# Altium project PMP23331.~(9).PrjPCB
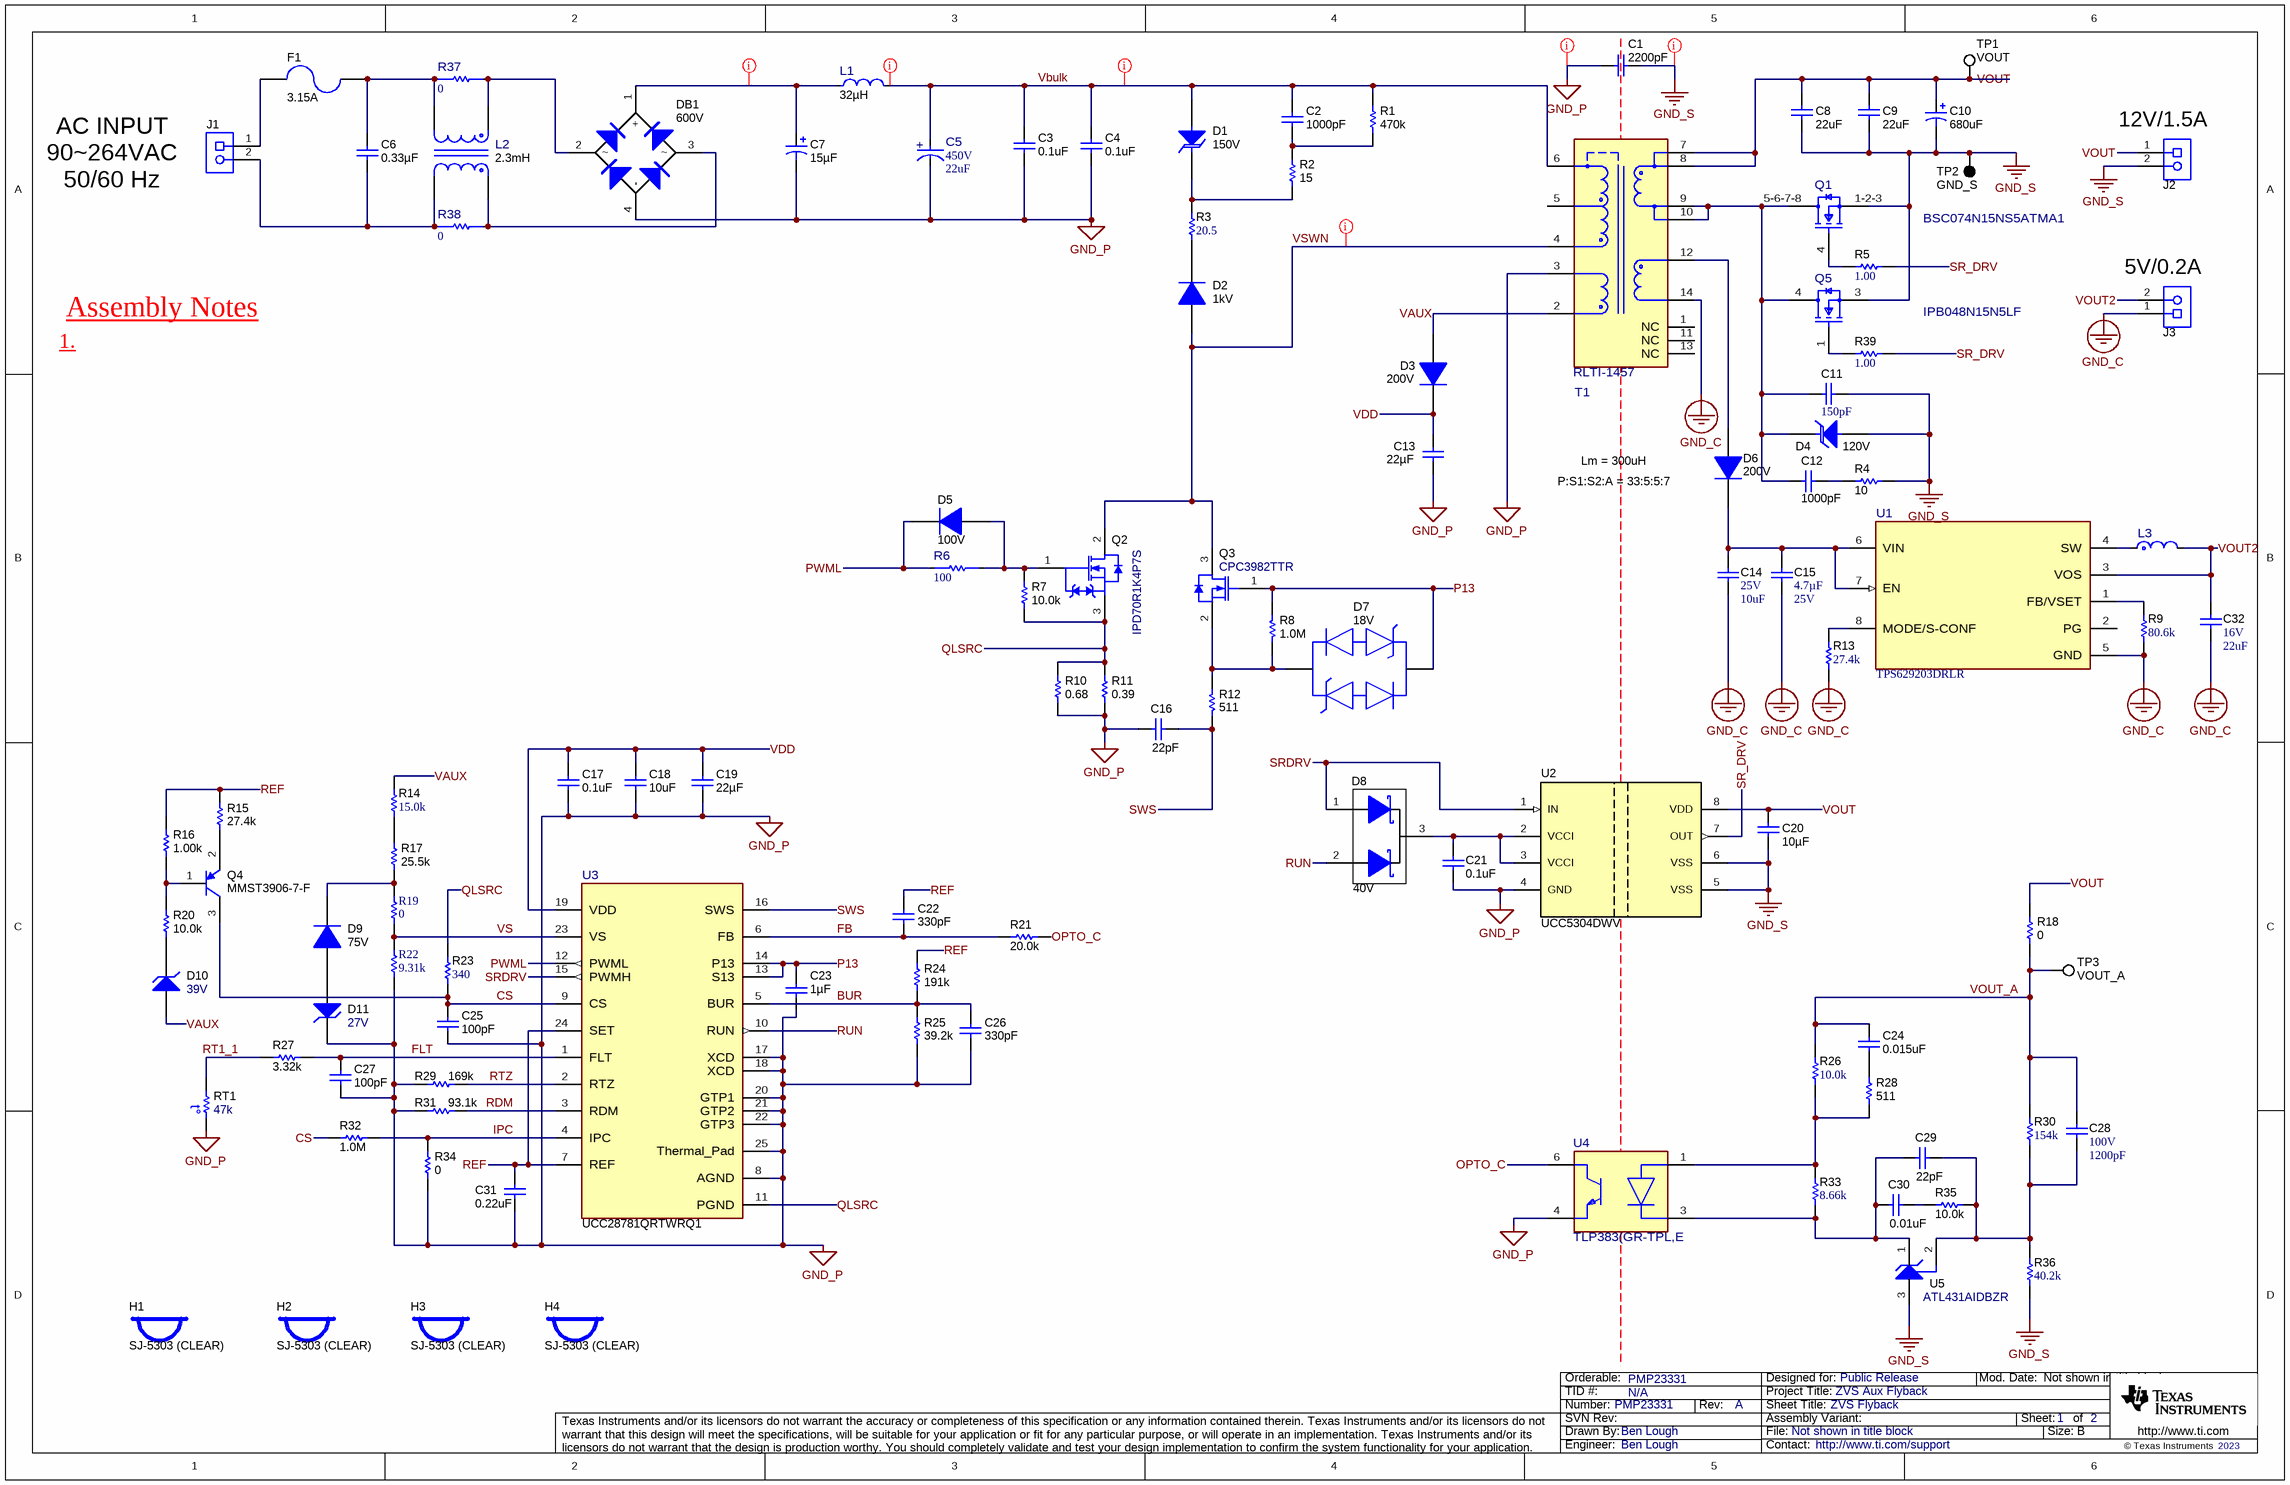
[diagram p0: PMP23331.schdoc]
=Drawn By: Ben Lough; CopyrightYear: 2023; EVM_orderable: PMP23331; PCB_Layout: Ben Lough; PCB_Rev: A; PRJ_Customer: Public Release; PRJ_Engineer: Ben Lough; PRJ_Number: PMP23331; PRJ_Title: ZVS Aux Flyback; SCH_Rev: A; TechSupport: http://www.ti.com/support; TID: N/A
1 sheet, 109 parts. Net scope: global (net labels, ports and power ports of the same name join across sheets).
Board file: PMP23331C.PcbDoc

## Sheet PMP23331.schdoc: ZVS Flyback
size 431 x 279 mm; Date: Not shown in title block; ApprovedBy: Not shown in title block; CheckedBy: Not shown in title block; Author: Not shown in title block; CompanyName: Not shown in title block; DrawnBy: Ben Lough; Engineer: Not shown in title block; Organization: Not shown in title block; Address1: Not shown in title block; Address2: Not shown in title block; Address3: Not shown in title block; Address4: Not shown in title block; DocumentNumber: 1; Revision: Use project parameter SCH_Rev; SheetNumber: 1; SheetTotal: 2; PageSetup: Record=PageOptions¦CenterHorizontal=True¦CenterVertical=True¦PrintScale=1.00¦XCorrection=1.00¦YCorrection=1.00¦PrintKind=0¦BorderSize=5000000¦LeftOffset=0¦BottomOffset=0¦Orientation=2¦PaperLength=1000¦PaperWidth=1000¦Scale=100¦PaperSource=15¦PrintQuality=600¦MediaType=1¦DitherType=10¦PaperKind=Letter¦PrintScaleMode=1

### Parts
C1  ValueDisplayed: 2200pF  [C900_9x13]  (hidden comment: C921U222MVVDBA7317)
C2  ValueDisplayed: 1000pF  [1206L]  (hidden comment: GRM31BR72J102KW01L)
C3  ValueDisplayed: 0.1uF  [1210_280]  (hidden comment: C1210C104KBRAC7800)
C4  ValueDisplayed: 0.1uF  [1210_280]  (hidden comment: C1210C104KBRAC7800)
C5  VDC_V: 450V  ValueDisplayed: 22uF  [FP-450BXW22MEFR18X16_RADIAL-MFG]  (hidden comment: 450BXW22MEFR18X16)
C6  ValueDisplayed: 0.33µF  [WCAP-FTX2_1500x850]  (hidden comment: 890324024003)
C7  ValueDisplayed: 15µF  [UVC_1000x1600]  (hidden comment: UVC2G150MPD)
C8  ValueDisplayed: 22uF  [1210_270L]  (hidden comment: GRM32ER71E226KE15L)
C9  ValueDisplayed: 22uF  [1210_270L]  (hidden comment: GRM32ER71E226KE15L)
C10  ValueDisplayed: 680uF  [PSG_1000x1150]  (hidden comment: APSG200ELL681MJB5S)
C11  Cap_F: 150pF  [0805_HV]  (hidden comment: 600F151FT250XT)
C12  ValueDisplayed: 1000pF  [0805L]  (hidden comment: GRM21AR72E102KW01D)
C13  ValueDisplayed: 22µF  [1210L]  (hidden comment: GMK325BJ226MM-P)
C14  VDC_V: 25V  ValueDisplayed: 10uF  [1210_280]  (hidden comment: C1210C106K3RACTU)
C15  Cap_F: 4.7µF  VDC_V: 25V  [0805L]  (hidden comment: CGA4J1X7R1E475K125AC)
C16  ValueDisplayed: 22pF  [0402S]  (hidden comment: GCM1555C1H220JA16D)
C17  ValueDisplayed: 0.1uF  [0402S]  (hidden comment: GRM155R71H104ME14D)
C18  ValueDisplayed: 10uF  [1206_180L]  (hidden comment: C3216X5R1H106K160AB)
C19  ValueDisplayed: 22µF  [1210L]  (hidden comment: GMK325BJ226MM-P)
C20  ValueDisplayed: 10µF  [1206_180L]  (hidden comment: C1206C106J3RACAUTO)
C21  ValueDisplayed: 0.1uF  [0402S]  (hidden comment: GRM155R71H104ME14D)
C22  ValueDisplayed: 330pF  [0402S]  (hidden comment: GRM155R71H331KA01D)
C23  Cap_F: 1µF  [0603S]  (hidden comment: CGA3E1X7R1V105K080AC)
C24  ValueDisplayed: 0.015uF  [0402S]  (hidden comment: GRM155R71H153KA12D)
C25  ValueDisplayed: 100pF  [0402S]  (hidden comment: GRM1555C1H101JA01D)
C26  ValueDisplayed: 330pF  [0402S]  (hidden comment: GRM155R71H331KA01D)
C27  ValueDisplayed: 100pF  [0402S]  (hidden comment: GRM1555C1H101JA01D)
C28  VDC_V: 100V  ValueDisplayed: 1200pF  [0402S]  (hidden comment: GRM155R72A122KA01D)
C29  ValueDisplayed: 22pF  [0402S]  (hidden comment: GCM1555C1H220JA16D)
C30  ValueDisplayed: 0.01uF  [0402S]  (hidden comment: GRM155R71H103KA88D)
C31  ValueDisplayed: 0.22uF  [0402S]  (hidden comment: GRM155R71C224KA12D)
C32  VDC_V: 16V  ValueDisplayed: 22uF  [1210_280]  (hidden comment: GCM32ER71C226KE19L)
D1  VRWM: 150V  [SMA]  (hidden comment: SMAJ150A)
D2  Vr_V: 1kV  [SMA]  (hidden comment: MRA4007T3G)
D3  Vr_V: 200V  [SOD-123H]  (hidden comment: CSFMT104-HF)
D4  value 120V  [SMA]  (hidden comment: SMAJ120A)
D5  Vr_V: 100V  [SOD-323]  (hidden comment: BAS316,115)
D6  Vr_V: 200V  [SOD-123H]  (hidden comment: CSFMT104-HF)
D7  value 18V  [FP-CDSOD323-T18C_SOD323-MFG]  (hidden comment: CDSOD323-T18C)
D8  Vr_V: 40V  [SOT-323]  (hidden comment: BAS40W-05-7-F)
D9  Vr_V: 75V  [SOD-523]  (hidden comment: 1N4148X-TP)
D10  value 39V  [SOD-523]  (hidden comment: BZT585B39T-7)
D11  value 27V  [SOD-323]  (hidden comment: SZMM3Z27VST1G)
DB1  value 600V  [Z4-D]  (hidden comment: Z4DGP406L-HF)
F1  Irating_A: 3.15A  [FUSE_392]  (hidden comment: 39213150000)
H1  SJ-5303 (CLEAR)  [Bumpon_SJ5003Transparent]
H2  SJ-5303 (CLEAR)  [Bumpon_SJ5003Transparent]
H3  SJ-5303 (CLEAR)  [Bumpon_SJ5003Transparent]
H4  SJ-5303 (CLEAR)  [Bumpon_SJ5003Transparent]
J1  ED120/2DS  [On-Shore_ED120_2DS]  (value not drawn)
J2  ED120/2DS  [On-Shore_ED120_2DS]  (value not drawn)
J3  ED120/2DS  [On-Shore_ED120_2DS]  (value not drawn)
L1  Ind_H: 32µH  [FP-7447052_PTH_D10MM0-MFG]  (hidden comment: 7447052)
L2  Ind_H: 2.3mH  [FP-RLTI-1387_PTH_CMC_0IN38_0IN60-MFG]  (hidden comment: RLTI-1387)
L3  XGL3530-332MEC  [FP-XGL3530_SMT_IND_3MM2_3MM5-MFG]  (value not drawn)
Q1  BSC074N15NS5ATMA1  [FP-BSC074N15NS5ATMA1_PG-TSON-8-3-MFG]
Q2  IPD70R1K4P7S  [DPAK]
Q3  CPC3982TTR  [SOT-23L]
Q4  MMST3906-7-F  [SOT-323]
Q5  IPB048N15N5LF  [FP-IPB042N10N3GATMA1_D2PAK-MFG]
R1  ValueDisplayed: 470k  [0805_HV1]  (hidden comment: CRCW0805470KJNEA)
R2  ValueDisplayed: 15  [0805_HV1]  (hidden comment: CRCW080515R0JNEA)
R3  ValueDisplayed: 20.5  [0805_HV]  (hidden comment: CRCW080520R5FKEA)
R4  ValueDisplayed: 10  [1206L]  (hidden comment: CRCW120610R0JNEA)
R5  ValueDisplayed: 1.00  [0402S]  (hidden comment: CSR0402FK1R00)
R6  Res_ohm: 100  [FP-RK73H1JTTD1000F_0603-MFG]  (hidden comment: RK73H1JTTD1000F)
R7  ValueDisplayed: 10.0k  [0402S]  (hidden comment: CRCW040210K0FKED)
R8  ValueDisplayed: 1.0M  [0402S]  (hidden comment: CRCW04021M00JNED)
R9  ValueDisplayed: 80.6k  [0402L]  (hidden comment: CRCW040280K6FKED)
R10  ValueDisplayed: 0.68  [0805_HV1]  (hidden comment: ERJ-6RQFR68V)
R11  ValueDisplayed: 0.39  [1210L]  (hidden comment: MCR25JZHFLR390)
R12  ValueDisplayed: 511  [0402S]  (hidden comment: CRCW0402511RFKED)
R13  ValueDisplayed: 27.4k  [0402L]  (hidden comment: CRCW040227K4FKED)
R14  ValueDisplayed: 15.0k  [0402]  (hidden comment: CRCW040215K0FKED)
R15  ValueDisplayed: 27.4k  [0402S]  (hidden comment: CRCW040227K4FKED)
R16  ValueDisplayed: 1.00k  [0402S]  (hidden comment: CRCW04021K00FKED)
R17  ValueDisplayed: 25.5k  [0402S]  (hidden comment: RC0402FR-0725K5L)
R18  ValueDisplayed: 0  [0402S]  (hidden comment: RC0402JR-070RL)
R19  value 0  [RESC1005X40X25NL05T10]  (hidden comment: RC0402JR-070RL)
R20  ValueDisplayed: 10.0k  [0402S]  (hidden comment: CRCW040210K0FKED)
R21  ValueDisplayed: 20.0k  [0402S]  (hidden comment: CRCW040220K0FKED)
R22  value 9.31k  [RESC1005X40X25LL05T05]  (hidden comment: ERJ-2RKF9311X)
R23  ValueDisplayed: 340  [0402S]  (hidden comment: CRCW0402340RFKED)
R24  ValueDisplayed: 191k  [0402S]  (hidden comment: CRCW0402191KFKED)
R25  ValueDisplayed: 39.2k  [0402S]  (hidden comment: CRCW040239K2FKED)
R26  ValueDisplayed: 10.0k  [0402S]  (hidden comment: RC0402FR-0710KL)
R27  ValueDisplayed: 3.32k  [0402S]  (hidden comment: CRCW04023K32FKED)
R28  ValueDisplayed: 511  [0402S]  (hidden comment: CRCW0402511RFKED)
R29  ValueDisplayed: 169k  [0402S]  (hidden comment: CRCW0402169KFKED)
R30  ValueDisplayed: 154k  [0402L]  (hidden comment: CRCW0402154KFKED)
R31  ValueDisplayed: 93.1k  [0402S]  (hidden comment: CRCW040293K1FKED)
R32  ValueDisplayed: 1.0M  [0402S]  (hidden comment: CRCW04021M00JNED)
R33  ValueDisplayed: 8.66k  [0402S]  (hidden comment: CRCW04028K66FKED)
R34  ValueDisplayed: 0  [0402S]  (hidden comment: CRCW04020000Z0EDHP)
R35  ValueDisplayed: 10.0k  [0402S]  (hidden comment: CRCW040210K0FKED)
R36  ValueDisplayed: 40.2k  [0402L]  (hidden comment: CRCW040240K2FKED)
R37  Res_ohm: 0  [FP-RMCF1206ZT0R00_1206-MFG]  (hidden comment: RMCF1206ZT0R00)
R38  Res_ohm: 0  [FP-RMCF1206ZT0R00_1206-MFG]  (hidden comment: RMCF1206ZT0R00)
R39  ValueDisplayed: 1.00  [0402S]  (hidden comment: CSR0402FK1R00)
RT1  value 47k  [0603S]  (hidden comment: NCP18WB473J03RB)
T1  RLTI-1457  [FP-RLTI-1457_PTH14_0IN93_0IN93-MFG]
TP1  VOUT  [Keystone5012]
TP2  GND_S  [Keystone5011]
TP3  VOUT_A  [Keystone5012]
U1  TPS629203DRLR  [DRL0008A-MFG]
U2  UCC5304DWV  [DWV0008A]
U3  UCC28781QRTWRQ1  [RTW0024B-MFG]
U4  TLP383(GR-TPL,E  [FP-TLP383(GR-TPL,E_SO6-4-MFG]
U5  ATL431AIDBZR  [DBZ0003A_L]

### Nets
GND_C: C14.2 C15.2 C32.2 J3.1 R9.1 R13.1 T1.14(SGND) U1.5(GND)
GND_P: C1.2 C3.1 C4.1 C5.1(CATHODE) C7.2(-) C13.1 C16.1 C17.2 C18.2 C19.1 C21.2 C23.2 C25.2 C26.2 C27.1 C31.2 D11.1(K) DB1.4(-) R10.2 R11.1 R22.1 R25.2 R29.1 R31.1 R34.1 RT1.2 T1.3(PGND) U2.4(GND) U3.8(AGND) U3.17(XCD) U3.18(XCD) U3.20(GTP1) U3.21(GTP2) U3.22(GTP3) U3.25(Thermal_Pad) U4.4(Emitter)
GND_S: C1.1 C8.2 C9.2 C10.2(-) C11.1 C20.2 D4.2(A) J2.2 Q1.1-2-3(S) Q5.3(SOURCE) R4.1 R36.1 TP2.1 U2.5(VSS) U2.6(VSS) U5.3(ANODE)
BUR: C26.1 R24.2 R25.1 U3.5(BUR)
CS: C25.1 Q4.3(C) R23.1 R32.2 U3.9(CS)
FB: C22.2 R21.1 U3.6(FB)
FLT: C27.2 R27.2 U3.1(FLT)
IPC: R32.1 R34.2 U3.4(IPC)
OPTO_C: R21.2 U4.6(Collector)
P13: C23.1 D7.2 Q3.1(G) R8.2 U3.13(S13) U3.14(P13)
PWML: D5.1(K) R6.1 U3.12(PWML)
QLSRC: Q2.3(S) R7.1 R10.1 R11.2 R23.2 U3.11(PGND)
RDM: R31.2 U3.3(RDM)
REF: C22.1 C31.1 R15.1 R16.1 R24.1 U3.7(REF) U3.24(SET)
RT1_1: R27.1 RT1.1
RTZ: R29.2 U3.2(RTZ)
RUN: D8.2(A) U3.10(RUN)
SR_DRV: R5.1 R39.1 U2.7(OUT)
SRDRV: D8.1(A) U2.1(IN) U3.15(PWMH)
SWS: C16.2 R12.1 U3.16(SWS)
VAUX: D3.2(A) D10.2(A) R14.2 T1.2(VAUX)
Vbulk: C2.1 C3.2 C4.2 C5.2(ANODE) D1.2(A) L1.2 R1.2 T1.6(VDC+)
VDD: C13.2 C17.1 C18.1 C19.2 D3.1(K) U3.19(VDD)
VOUT: C8.1 C9.1 C10.1(+) C20.1 J2.1 R18.1 T1.7(12V) T1.8(12V) TP1.1 U2.8(VDD)
VOUT2: C32.1 J3.2 L3.2 U1.3(VOS)
VOUT_A: C24.2 C28.1 R18.2 R26.2 R30.2 TP3.1
VS: R19.1 R22.2 U3.23(VS)
VSWN: D2.2(A) Q2.2(D) Q3.3(D) T1.4(DRAIN)
NetC2_2: C2.2 R1.1 R2.2
NetC6_1: C6.1 J1.2 L2.2 R38.1
NetC6_2: C6.2 F1.1 L2.3 R37.1
NetC7_1: C7.1(+) DB1.1(+) L1.1
NetC11_2: C11.2 C12.2 D4.1(K) Q1.5-6-7-8(D) Q5.4(DRAIN) T1.9(SR_FET) T1.10(SR_FET)
NetC12_1: C12.1 R4.2
NetC14_1: C14.1 C15.1 D6.1(K) U1.6(VIN) U1.7(EN)
NetC21_1: C21.1 D8.3(K) U2.2(VCCI) U2.3(VCCI)
NetC24_1: C24.1 R28.2
NetC28_2: C28.2 C29.2 R30.1 R35.2 R36.2 U5.2(REF)
NetC29_1: C29.1 C30.2 R33.1 U4.3(Cathode) U5.1(CATHODE)
NetC30_1: C30.1 R35.1
NetD1_1: D1.1(K) R2.1 R3.2
NetD2_1: D2.1(K) R3.1
NetD5_2: D5.2(A) Q2.1(G) R6.2 R7.2
NetD6_2: D6.2(A) T1.12(12V)
NetD7_1: D7.1 Q3.2(S) R8.1 R12.2
NetD9_1: D9.1(K) R17.2 R19.2
NetD9_2: D9.2(A) D11.2(A)
NetD10_1: D10.1(K) R20.2
NetDB1_2: DB1.2 L2.4 R37.2
NetDB1_3: DB1.3 L2.1 R38.2
NetF1_2: F1.2 J1.1
NetL3_1: L3.1 U1.4(SW)
NetQ1_4: Q1.4(G) R5.2
NetQ4_1: Q4.1(B) R16.2 R20.1
NetQ4_2: Q4.2(E) R15.2
NetQ5_1: Q5.1(GATE) R39.2
NetR9_2: R9.2 U1.1(FB/VSET)
NetR13_2: R13.2 U1.8(MODE/S-CONF)
NetR14_1: R14.1 R17.1
NetR26_1: R26.1 R28.1 R33.2 U4.1(Anode)

Not connected (* = marked no-connect by the designer): T1 1(NC) 5 11(NC) 13(NC); U1 2(PG)

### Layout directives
net class HV: NetC7_1, Vbulk, VSWN
net class Primary: GND_P
net class Secondary: GND_S

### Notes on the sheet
- 90|64VAC
- AC INPUT
- (near J2) 12V/1.5A
- 50/60 Hz
- Assembly Notes
- (near J3) 5V/0.2A
- 1.
- P:S1:S2:A = 33:5:5:7
- Lm = 300uH

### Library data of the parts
C1 = CMP-0078358-1: CAP, CERM, 2200 pF, X1 400 VAC/Y1 400 VAC, +/- 20%, Y5V, D9xL13mm; Manufacturer: Kemet; Cap_F: 2.2nF; SizeAreaWB_mm2: 121; VAC_X: 400V; SizeArea_mm2: 81; AEC Qualified: N; AEC Category: Q200; Value: 2200pF; TaMax_C: 125°C; SizeZ_mm: 13; TaMin_C: -40°C; SizeY_mm: 9; U/M: EA; AC_Safety: X1Y1; Cap_Case: 9x13mm
C2 = CMP-0008909-2: CAP, CERM, 1000 pF, 630 V, +/- 10%, X7R, 1206; Manufacturer: MuRata; TaMin_C: -55°C; Polarized: N; SizeAreaWB_mm2: 10.92; Value1: Unknown; U/M: EA; Value: 1000pF; TaMax_C: 125°C; SizeZ_mm: 1.35; SizeX_mm: 3.2; SizeY_mm: 1.6; Cap_Case: 1206; Value2: 630V; SizeArea_mm2: 5.12; Cap_F: 1nF; AEC Category: Q200
C3 C4 = CMP-0009076-1: CAP, CERM, 0.1 uF, 630 V, +/- 10%, X7R, 1210; Manufacturer: Kemet; Polarized: N; Value: 0.1uF; U/M: EA; Cap_F: 100nF; Value1: Unknown; VDC_V: 630V; TaMin_C: -55°C; TaMax_C: 125°C; Cap_Case: 1210; SizeArea_mm2: 8; SizeAreaWB_mm2: 14.7; SizeX_mm: 3.2; SizeY_mm: 2.5; SizeZ_mm: 2.8; AEC Category: Q200
C5 = CMP-0088960-1: Cap Aluminum Lytic 22uF 450V 20% (18 X 16mm) Radial 7.5mm 340mA 10000h 105C; Manufacturer: Rubycon; Cap_F: 22µF; Dissipation Factor: 25%; IRMS_A: 850mA; SizeZ_mm: 18mm; Leakage Current: 298uA; Life: 10000Hours; AEC Qualified: No
C6 = CMP-0084596-1: CAP, Film, 0.33 µF, X2 275 VAC, +/- 10%, TH; Manufacturer: Wurth Elektronik; Cap_Case: 15x8.5mm; SizeAreaWB_mm2: 178.5; AEC Qualified: N; SizeX_mm: 15; Cap_F: 330nF; SizeY_mm: 8.5; VAC_X: 275; TaMin_C: -40°C; SizeZ_mm: 14.5; SizeArea_mm2: 127.5; Value: 0.33uF; TaMax_C: 105°C; AEC Category: Q200
C7 = CMP-0860955-2: CAP, AL, 15 µF, 400 V, +/- 20%, AEC-Q200 Grade 2, TH; Manufacturer: Nichicon; SizeArea_mm2: 100; CompType: Capacitor; Value2: 400V; SizeZ_mm: 18; IRMS_A: 180mA; Polarized: Y; SizeX_mm: 10; Value: 15uF; TaMin_C: -40°C; AEC Grade: 2; U/M: EA; SizeAreaWB_mm2: 144; Cap_Case: 10x16; TaMax_C: 105°C; AEC Category: Q200
C8 C9 = CMP-0009224-2: CAP, CERM, 22 uF, 25 V, +/- 10%, X7R, 1210; Manufacturer: MuRata; TaMin_C: -55°C; Polarized: N; SizeAreaWB_mm2: 14.7; Value1: Unknown; U/M: EA; Value: 22uF; TaMax_C: 125°C; SizeZ_mm: 2.7; SizeX_mm: 3.2; SizeY_mm: 2.5; Cap_Case: 1210; Value2: 25V; SizeArea_mm2: 8; Cap_F: 22µF; AEC Category: Q200
C10 = CMP-0012176-3: CAP, Aluminum Polymer, 680 uF, 20 V, +/- 20%, 0.012 ohm, TH; Manufacturer: Chemi-Con; TaMin_C: -55°C; ESR_ohm: 0.012; Polarized: Y; SizeAreaWB_mm2: 144; Value: 680uF; TaMax_C: 105°C; SizeZ_mm: 13; SizeX_mm: 10; Cap_Case: 10x11.5; Value2: 20V; SizeArea_mm2: 100; CompType: Capacitor; AEC Qualified: N; Cap_F: 680µF; IRMS_A: 5.4A; AEC Category: Q200
C11 = CMP-0064943-2: CAP, CERM, 150 pF, 250 V,+/- 10%, X7R, 0805; Manufacturer: TDK; TaMin_C: -55°C; Polarized: N; SizeAreaWB_mm2: 6.75; Value1: Unknown; U/M: EA; Value: 1000pF; TaMax_C: 125°C; SizeZ_mm: 1.45; SizeX_mm: 2; SizeY_mm: 1.25; Cap_Case: 0805; Value2: 250V; SizeArea_mm2: 2.5; AEC Category: Q200
C12 = CMP-0008251-2: CAP, CERM, 1000 pF, 250 V, +/- 10%, X7R, 0805; Manufacturer: MuRata; TaMin_C: -55°C; Polarized: N; SizeAreaWB_mm2: 6.75; Value1: Unknown; U/M: EA; Value: 1000pF; TaMax_C: 125°C; SizeZ_mm: 1.45; SizeX_mm: 2; SizeY_mm: 1.25; Cap_Case: 0805; Value2: 250V; SizeArea_mm2: 2.5; Cap_F: 1nF; AEC Category: Q200
C13 C19 = CMP-0085817-1: CAP, CERM, 22 µF, 35 V,+/- 20%, X5R, 1210; Manufacturer: Taiyo Yuden; Value: 22uF; VDC_V: 35V; SizeZ_mm: 1.35; Cap_Case: 1210; TaMax_C: 85°C; U/M: EA; SizeAreaWB_mm2: 14.7; SizeX_mm: 3.2; SizeArea_mm2: 8; TaMin_C: -55°C; AEC Qualified: N; SizeY_mm: 2.5; AEC Category: Q200
C14 = CMP-0009078-1: CAP, CERM, 10 uF, 25 V, +/- 10%, X7R, 1210; Manufacturer: Kemet; TaMin_C: -55°C; Polarized: N; SizeAreaWB_mm2: 14.7; Value1: Unknown; U/M: EA; Value: 10uF; TaMax_C: 125°C; SizeZ_mm: 2.8; SizeX_mm: 3.2; SizeY_mm: 2.5; Cap_Case: 1210; SizeArea_mm2: 8; Cap_F: 10µF; AEC Category: Q200
C15 = CMP-0076706-1: CAP, CERM, 4.7 µF, 25 V,+/- 10%, X7R, AEC-Q200 Grade 1, 0805; Manufacturer: TDK; SizeAreaWB_mm2: 6.75; SizeArea_mm2: 2.5; AEC Qualified: Y; AEC Category: Q200; Value: 4.7uF; TaMax_C: 125°C; SizeZ_mm: 1.45; AEC Grade: 1; Polarized: N; TaMin_C: -55°C; SizeY_mm: 1.25; U/M: EA; SizeX_mm: 2.0; Cap_Case: 2x1.25x1.25mm
C16 C29 = CMP-0006348-2: CAP, CERM, 22 pF, 50 V, +/- 5%, C0G/NP0, AEC-Q200 Grade 1, 0402; Manufacturer: MuRata; TaMin_C: -55°C; Polarized: N; SizeAreaWB_mm2: 3; Value1: Unknown; U/M: EA; Value: 22pF; TaMax_C: 125°C; SizeZ_mm: 0.6; SizeX_mm: 1; SizeY_mm: 0.5; Cap_Case: 0402; Value2: 50V; AEC Qualified: Y; AEC Category: Q200
C17 C21 = CMP-0006675-2: CAP, CERM, 0.1 uF, 50 V, +/- 20%, X7R, 0402; Manufacturer: MuRata; TaMin_C: -55°C; Polarized: N; SizeAreaWB_mm2: 3; Value1: Unknown; U/M: EA; Value: 0.1uF; TaMax_C: 125°C; SizeZ_mm: 0.6; SizeX_mm: 1; SizeY_mm: 0.5; Cap_Case: 0402; Value2: 50V; Cap_F: 100nF; AEC Category: Q200
C18 = CMP-0008658-2: CAP, CERM, 10 uF, 50 V, +/- 10%, X5R, 1206; Manufacturer: TDK; TaMin_C: -55°C; ESR_ohm: 2.229m; Polarized: N; SizeAreaWB_mm2: 10.92; Value1: 0.002229 ohm; U/M: EA; Value: 10uF; TaMax_C: 85°C; SizeZ_mm: 1.8; SizeX_mm: 3.2; SizeY_mm: 1.6; Cap_Case: 1206_180; Value2: 50V; SizeArea_mm2: 5.12; Cap_F: 10µF; IRMS_A: 4.85932A; AEC Category: Q200
C20 = CMP-0081062-1: CAP, CERM, 10 µF, 25 V,+/- 5%, X7R, AEC-Q200 Grade 1, 1206; Manufacturer: Kemet; TaMin_C: -55°C; Polarized: N; SizeAreaWB_mm2: 10.92; U/M: EA; Value: 10uF; TaMax_C: 125°C; SizeZ_mm: 1.8; SizeX_mm: 3.2; SizeY_mm: 1.6; Cap_Case: 1206_180; Value2: 25V; SizeArea_mm2: 5.12; AEC Qualified: Y; AEC Grade: 1; AEC Category: Q200
C22 C26 = CMP-0006687-2: CAP, CERM, 330 pF, 50 V, +/- 10%, X7R, 0402; Manufacturer: MuRata; TaMin_C: -55°C; Polarized: N; SizeAreaWB_mm2: 3; Value1: Unknown; U/M: EA; Value: 330pF; TaMax_C: 125°C; SizeZ_mm: 0.6; SizeX_mm: 1; SizeY_mm: 0.5; Cap_Case: 0402; Value2: 50V; AEC Category: Q200
C23 = CMP-0007067-4: CAP, CERM, 1 uF, 35 V, +/- 10%, X7R, AEC-Q200 Grade 1, 0603; Manufacturer: TDK; TaMin_C: -55°C; ESR_ohm: 5.522m; Polarized: N; SizeAreaWB_mm2: 4.68; Value1: 0.005522 ohm; U/M: EA; Value: 1uF; TaMax_C: 125°C; SizeZ_mm: 1; SizeX_mm: 1.6; SizeY_mm: 0.8; Cap_Case: 0603; Value2: 35V; SizeArea_mm2: 1.28; AEC Qualified: Y; IRMS_A: 2.21617A; AEC Category: Q200
C24 = CMP-0006679-2: CAP, CERM, 0.015 uF, 50 V, +/- 10%, X7R, 0402; Manufacturer: MuRata; TaMin_C: -55°C; Polarized: N; SizeAreaWB_mm2: 3; Value1: Unknown; U/M: EA; TaMax_C: 125°C; SizeZ_mm: 0.6; SizeX_mm: 1; SizeY_mm: 0.5; Cap_Case: 0402; Value2: 50V; Cap_F: 15nF; AEC Category: Q200
C25 C27 = CMP-0006410-2: CAP, CERM, 100 pF, 50 V, +/- 5%, C0G/NP0, 0402; Manufacturer: MuRata; TaMin_C: -55°C; Polarized: N; SizeAreaWB_mm2: 3; Value1: Unknown; U/M: EA; Value: 100pF; TaMax_C: 125°C; SizeZ_mm: 0.6; SizeX_mm: 1; SizeY_mm: 0.5; Cap_Case: 0402; Value2: 50V; AEC Category: Q200
C28 = CMP-0006700-2: CAP, CERM, 1200 pF, 100 V, +/- 10%, X7R, 0402; Manufacturer: MuRata; TaMin_C: -55°C; Polarized: N; SizeAreaWB_mm2: 3; Value1: Unknown; U/M: EA; Value: 1200pF; TaMax_C: 125°C; SizeZ_mm: 0.6; SizeX_mm: 1; SizeY_mm: 0.5; Cap_Case: 0402; Cap_F: 1.2nF; AEC Category: Q200
C30 = CMP-0006674-2: CAP, CERM, 0.01 uF, 50 V, +/- 10%, X7R, 0402; Manufacturer: MuRata; TaMin_C: -55°C; Polarized: N; SizeAreaWB_mm2: 3; Value1: Unknown; U/M: EA; Value: 0.01uF; TaMax_C: 125°C; SizeZ_mm: 0.6; SizeX_mm: 1; SizeY_mm: 0.5; Cap_Case: 0402; Value2: 50V; Cap_F: 10nF; AEC Category: Q200
C31 = CMP-0006648-2: CAP, CERM, 0.22 uF, 16 V, +/- 10%, X7R, 0402; Manufacturer: MuRata; TaMin_C: -55°C; Polarized: N; SizeAreaWB_mm2: 3; Value1: Unknown; U/M: EA; Value: 0.22uF; TaMax_C: 125°C; SizeZ_mm: 0.6; SizeX_mm: 1; SizeY_mm: 0.5; Cap_Case: 0402; Value2: 16V; Cap_F: 220nF; AEC Category: Q200
C32 = CMP-0009174-2: CAP, CERM, 22 uF, 16 V, +/- 10%, X7R, 1210; Manufacturer: MuRata; TaMin_C: -55°C; Polarized: N; SizeAreaWB_mm2: 14.7; Value1: Unknown; U/M: EA; Value: 22uF; TaMax_C: 125°C; SizeZ_mm: 2.8; SizeX_mm: 3.2; SizeY_mm: 2.5; Cap_Case: 1210; SizeArea_mm2: 8; Cap_F: 22µF; AEC Category: Q200
D1 = CMP-0084982-1: Diode, TVS, Uni, 150 V, 243 Vc, 400 W, 1.6 A, SMA; Manufacturer: Littelfuse; Vc: 243V; Ipp: 1.6A; RJA_CperW: 120; AEC Qualified: N; Value: 150V; Ppk: 400W; AEC Category: Q101; SizeArea_mm2: 16.3228; SizeAreaWB_mm2: 37.3428; SizeZ_mm: 2.87; Vbr_Max: 185V; SizeX_mm: 5.59; SizeY_mm: 2.92; Vbr_Min: 167V
D2 = CMP-0077082-2: Diode, Standard Recovery Rectifier, 1000 V, 1 A, AEC-Q101, SMA; Manufacturer: ON Semiconductor; SizeAreaWB_mm2: 37.3428; SizeArea_mm2: 16.3228; AEC Qualified: Y; TJmax_C: 175°C; AEC Category: Q101; Value: 1000V; SizeZ_mm: 2.87; Green_REACh: Passed; Io_A: 1A; Vf_V: 1.1V; SizeY_mm: 2.92; Green_Lifecycle: Active; SizeX_mm: 5.59; RJC_CperW: 16.2
D3 D6 = CMP-0029199-2: Diode, Superfast Rectifier, 200 V, 1 A, 3.5x1.6mm; Manufacturer: Comchip Technology; Vf_V: 950mV; Value: 200V; Value1: 1A; Value2: 0.95V; TJmax_C: 150°C; SizeAreaWB_mm2: 11.7; SizeArea_mm2: 5.6; SizeX_mm: 3.5; SizeY_mm: 1.6; SizeZ_mm: 1; AEC Category: Q101; AEC Qualified: N
D4 = CMP-0084980-1: Diode, TVS, Uni, 120 V, 193 Vc, 400 W, 2.1 A, SMA; Manufacturer: Littelfuse; SizeX_mm: 5.59; Vc: 193V; Ipp: 2.1A; Vbr_Max: 147V; AEC Qualified: N; Vbr_Min: 133V; SizeY_mm: 2.92; Ppk: 400W; SizeZ_mm: 2.87; AEC Category: Q101; SizeAreaWB_mm2: 37.3428; RJA_CperW: 120; SizeArea_mm2: 16.3228
D5 = CMP-0029006-2: Diode, Ultrafast, 100 V, 0.25 A, SOD-323; Manufacturer: Nexperia; SizeY_mm: 1.35; Value1: 0.25A; SizeAreaWB_mm2: 8.695; SizeZ_mm: 1; Io_A: 250mA; Value2: 1.4V; SizeX_mm: 2.7; Green_REACh: Incomplete; TJmax_C: 150°C; Green_Lifecycle: Not Set; AEC Category: Q101; Value: 100V; SizeArea_mm2: 3.645
D7 = CMP-0087587-1: Diode, TVS, Bi, 18 V, SOD-323; Manufacturer: Bourns Inc.; SizeZ_mm: 1.14mm; AEC Qualified: No
D8 = CMP-0028437-2: Diode, Schottky, 40 V, 0.2 A, SOT-323; Manufacturer: Diodes Inc.; Io_A: 200mA; Green_Lifecycle: Not Set; SizeAreaWB_mm2: 10.24; Green_REACh: Incomplete; Value1: 0.2A; Value: 40V; SizeZ_mm: 1.1; SizeX_mm: 2.2; Vf_V: 800mV; Value2: 0.8V; SizeArea_mm2: 4.84; AEC Category: Q101
D9 = CMP-0076957-3: Diode, Switching, 75 V, 0.3 A, SOD-523; Manufacturer: Micro Commercial Components; SizeY_mm: 0.9; Value2: 1.25V; Value1: 0.3A; Value: 75V; Green_Lifecycle: Not Set; SizeAreaWB_mm2: 5.13; SizeArea_mm2: 1.53; SizeZ_mm: 0.65; Io_A: 300mA; TJmax_C: 150°C; SizeX_mm: 1.7; Green_REACh: Incomplete; AEC Category: Q101
D10 = CMP-0005889-5: Diode, Zener, 39 V, 350 mW, AEC-Q101, SOD-523; Manufacturer: Diodes Inc.; SizeZ_mm: 0.65; Value1: 0.35W; SizeAreaWB_mm2: 5.13; SizeY_mm: 0.9; AEC Qualified: Y; SizeX_mm: 1.7; SizeArea_mm2: 1.53; Power_W: 350mW; AEC Category: Q101; RJA_CperW: 357
D11 = CMP-0085774-1: Diode, Zener, 27 V, 300 mW, AEC-Q101, SOD-323; Manufacturer: ON Semiconductor; AEC Qualified: Y; Value1: 0.3W; SizeX_mm: 2.7; SizeZ_mm: 1; SizeArea_mm2: 3.645; SizeAreaWB_mm2: 8.695; RJA_CperW: 416; SizeY_mm: 1.35; Power_W: 300mW; AEC Category: Q101
DB1 = Z4DGP406L-HF: Diode, P-N-Bridge, 600 V, 4 A, Z4-D; Manufacturer: Comchip Technology; U/M: EA; Vf_V: 0.95; Value1: 4A; Value2: 0.95V; Io_A: 4; Vr_V: 600; TJmax_C: 175; SizeAreaWB_mm2: 126.25; SizeArea_mm2: 85.05; SizeX_mm: 10.5; SizeY_mm: 8.1; SizeZ_mm: 1.55; AEC Category: Q101; AEC Qualified: N; Green_Lifecycle: Not Set; Green_REACh: Incomplete
F1 = CMP-0003561-2: Fuse, 3.15 A, 250VAC/VDC, TH; Manufacturer: Littelfuse; VAC_V: 250V
H1-H4 = CMP-0003620-1: Bumpon, Hemisphere, 0.44 X 0.20, Clear; Manufacturer: 3M
J1-J3 = CMP-0074910-1: Terminal Block, 5.08 mm, 2x1, Brass, TH; Manufacturer: On-Shore Technology; Pitch_mm: 5.08; Gender: Female; Shrouded: N; Row_Count: 1; Current_A: 15A; Voltage_V: 300V; Cert_CULUS: Y; CNHeader: False; CT: True; Green_Lifecycle: Not Set; Green_REACh: Incomplete
L1 = CMP-0087546-1: WE-FI Leaded Toroidal Line Choke; Manufacturer: Wurth; SizeZ_mm: 10mm; Irms: 2.6A; DCR_ohm: 0.045; AEC Qualified: No; Symbol Name: SYM-7447052
L2 = CMP-0092946-1: Common Mode Choke, 2.3mH 35%, 0.6x0.38x0.75 IN; Manufacturer: Renco; Test Frequency: 10kHz; SizeZ_mm: 0.75inch; DCR_ohm: 0.03; AEC Qualified: No
L3 = CMP-0092762-2: Power Inductor, shielded, composite, 20% tol, SMT, RoHS, halogen-free   USD 0.580; Manufacturer: Coilcraft; Ind_H: 3.3µH; Value: 3.3uH; Self Resonant Frequency: 43MHz; TaMax_C: +125°C; TaMin_C: -40°C; AEC Qualified: Yes; Isat: 1.6A; DCR_ohm: 37.4m; SizeZ_mm: 3mm; Irms: 5.4A; Test Frequency: 1MHz; Shrouded: true; AEC Grade: Grade 1
Q1 = CMP-0092601-1: N-Channel 150 V 114A (Tc) 214W (Tc) Surface Mount, Wettable Flank PG-TSON-8-3; Manufacturer: Infineon; Threshold Vgs Min: 3V; Pulse Drain Current: 456A; Drain To Source Breakdown Voltage: 150V; AEC Qualified: No; Input Capacitace At Vds: 3100pF @ 75V; VdsMax_V: 1.2V; Rdson45_ohm: 6m; Turn On Delay Time: 9ns; Vgs_V: 20V; Reverse Recovery Charge: 23nC; Threshold Vgs Max: 4.6V; Transconductance: 81S; Turn Off Delay Time: 15ns; Number Of Channels: 1; Typ Forward Diode Voltage: 0.85V; Rthja Max: 50°C/W; SizeZ_mm: 1.1mm; Reverse Recovery Time: 29ns; ChMode: False; QgTyp_nC: 41nC @ 10V; TJmax_C: +175°C
Q2 = CMP-0083711-2: MOSFET, N-CH, 700 V DPAK; Manufacturer: Infineon Technologies; Alternate Manufacturer: None; AEC Qualified: N; Vgs_V: 20V; SizeY_mm: 6.54; VdsMax_V: 800V; IdsMax_A: 8A; SizeX_mm: 9.91; Value2: 20 nC; AEC Category: Q101; ChMode: Enhancement; SizeAreaWB_mm2: 101.7114; Value1: ? ohm; SizeArea_mm2: 64.8114; Value: 800V; SizeZ_mm: 2.29; QgTyp_nC: 20
Q3 = CMP-0081263-2: MOSFET, N-CH, Depletion Mode, 800 V, SOT-23; Alternate Manufacturer: None; Manufacturer: IXYS; SizeAreaWB_mm2: 14; Vgs_V: 15V; Value1: ? ohm; VdsMax_V: 800V; Value: 800V; SizeZ_mm: 1.1; SizeX_mm: 2.5; SizeY_mm: 3; Value2: ? nC; SizeArea_mm2: 7.5; ChType: N; AEC Category: Q101
Q4 = CMP-0077878-2: Transistor, PNP, 40 V, 0.2 A, AEC-Q101, SOT-323; Manufacturer: Diodes Inc.; Vcesat1_V: 300mV; AEC Qualified: Y; CompType: BJT; PNP: 1.0; Vceo_V: 40V; AEC Category: Q101; NPN: 0.0; Value1: 0.2 A; HfeMax: 300.0; TaMax_C: 150°C; SizeAreaWB_mm2: 10.24; SizeZ_mm: 1.1; SizeY_mm: 2.2; Value: 40 V; SizeArea_mm2: 4.84; IcRated_A: 200mA; TaMin_C: -55°C
Q5 = CMP-0087591-1: N-Channel 100V 100A (Tc) 214W (Tc) Surface Mount D²PAK (TO-263AB); Manufacturer: Infineon; Transconductance: 145S; Turn Off Delay Time: 48ns; IdsMax_A: 137A; TJmax_C: +175°C; Pulse Drain Current: 548A; Threshold Vgs Max: 3.5V; Rdson45_ohm: 3.6mΩ; Typ Forward Diode Voltage: 1V; Standoff Height: 0mm; QgTyp_nC: 88nC @ 10V; Reverse Recovery Time: 68ns; Import Ts: 1521842123; SizeZ_mm: 4.7mm; Input Capacitace At Vds: 6320pF @ 50V; Rthja Max: 62K/W; Threshold Vgs Min: 2V; Reverse Recovery Charge: 135nC; Number Of Channels: 1; Ciiva Ids: 4154385; ChMode: False; AEC Qualified: No; Max Forward Diode Voltage: 1.2V; Turn On Delay Time: 27ns; Vgs_V: 20V
R1 = CMP-0020554-3: RES, 470 k, 5%, 0.125 W, AEC-Q200 Grade 0, 0805; Manufacturer: Vishay-Dale; Power_W: 125mW; TempCo: 200 ppm/C; Value: 470k; EIA_Code: E24; SizeX_mm: 2; SizeY_mm: 1.25; SizeZ_mm: 1.45; Value2: 0.125W; SizeArea_mm2: 2.5; AEC Qualified: Y; VDC_V: 150V; AEC Category: Q200; AEC Grade: 0
R2 = CMP-0020464-3: RES, 15, 5%, 0.125 W, AEC-Q200 Grade 0, 0805; Manufacturer: Vishay-Dale; Power_W: 125mW; TempCo: 200 ppm/C; Value_Code: 15R0; Value: 15; EIA_Code: E24; SizeX_mm: 2; SizeY_mm: 1.25; SizeZ_mm: 1.45; Value2: 0.125W; SizeArea_mm2: 2.5; AEC Qualified: Y; VDC_V: 150V; AEC Category: Q200; AEC Grade: 0
R3 = CMP-0021045-3: RES, 20.5, 1%, 0.125 W, AEC-Q200 Grade 0, 0805; Manufacturer: Vishay-Dale; Power_W: 125mW; TempCo: 100 ppm/C; Value_Code: 20R5; Value: 20.5; EIA_Code: E96; SizeX_mm: 2; SizeY_mm: 1.25; SizeZ_mm: 1.45; Value2: 0.125W; SizeArea_mm2: 2.5; AEC Qualified: Y; VDC_V: 150V; AEC Category: Q200; AEC Grade: 0
R4 = CMP-0018578-3: RES, 10, 5%, 0.25 W, AEC-Q200 Grade 0, 1206; Manufacturer: Vishay-Dale; Power_W: 250mW; TempCo: 200 ppm/C; Value_Code: 10R0; Value: 10; EIA_Code: E24; SizeX_mm: 3.2; SizeY_mm: 1.6; SizeZ_mm: 1.35; Value2: 0.25W; SizeArea_mm2: 5.12; AEC Qualified: Y; VDC_V: 200V; AEC Category: Q200; AEC Grade: 0
R5 R39 = CMP-0081622-1: RES, 1.00, 1%, 0.125 W, 0402; Manufacturer: Stackpole Electronics Inc; Value_Code: 1R00; SizeAreaWB_mm2: 3; SizeArea_mm2: 0.5; AEC Qualified: N; AEC Category: Q200; Res_ohm: 1; Value: 1.00; SizeZ_mm: 0.6; EIA_Code: E96; TempCo: 200 ppm/C; Power_W: 125mW; VDC_V: 200V; Value2: 0.125W
R6 = CMP-0089152-1: 100 Ohms ±1% 0.125W, 1/8W Chip Resistor 0603 (1608 Metric) Automotive AEC-Q200, Moisture Resistant Thick Film; Manufacturer: KOA Speer; Approved Alternate Part Number: 541-1.00HHCT-ND; Power: 100mW; Voltage: 75V; AEC Qualified: Yes; AEC Grade: Grade 0; SizeZ_mm: 0.5mm; TempCo: 100ppm/°C; Standoff Height: 0mm
R7 R20 R35 = CMP-0025958-3: RES, 10.0 k, 1%, 0.063 W, AEC-Q200 Grade 0, 0402; Manufacturer: Vishay-Dale; Power_W: 63mW; TempCo: 100 ppm/C; Value_Code: 10k0; Value: 10.0k; EIA_Code: E96; Res_ohm: 10k; SizeX_mm: 1; SizeY_mm: 0.5; SizeZ_mm: 0.6; Value2: 0.063W; AEC Qualified: Y; VDC_V: 50V; AEC Category: Q200; AEC Grade: 0
R8 = CMP-0026859-2: RES, 1.0 M, 5%, 0.063 W, AEC-Q200 Grade 0, 0402; Manufacturer: Vishay-Dale; Value: 1.0Meg; Res_ohm: 1M; Value_Code: 1M00; Power_W: 63mW; Value2: 0.063W; VDC_V: 50V; TempCo: 200 ppm/C; SizeArea_mm2: 0.5; SizeX_mm: 1; SizeZ_mm: 0.6; EIA_Code: E24; AEC Category: Q200; AEC Qualified: Y; AEC Grade: 0
R9 = CMP-0026570-2: RES, 80.6 k, 1%, 0.063 W, AEC-Q200 Grade 0, 0402; Manufacturer: Vishay-Dale; Power_W: 63mW; TempCo: 100 ppm/C; Value_Code: 80k6; Value: 80.6k; EIA_Code: E96; SizeX_mm: 1; SizeY_mm: 0.5; SizeZ_mm: 0.6; Value2: 0.063W; AEC Qualified: Y; VDC_V: 50V; AEC Category: Q200; AEC Grade: 0
R10 = CMP-0021844-3: RES, 0.68, 1%, 0.125 W, AEC-Q200 Grade 0, 0805; Manufacturer: Panasonic; Power_W: 125mW; TempCo: 250 ppm/C; Value_Code: R680; Value: 0.68; EIA_Code: E96; SizeX_mm: 2; SizeY_mm: 1.25; SizeZ_mm: 1.45; Value2: 0.125W; SizeArea_mm2: 2.5; AEC Qualified: Y; AEC Category: Q200; AEC Grade: 0; SizeAreaWB_mm2: 6.75
R11 = CMP-0015175-2: RES, 0.39, 1%, 0.5 W, 1210; Manufacturer: Rohm; PartNumber: MCR25JZHFLR220; Power_W: 500mW; TempCo: 200 ppm/C; SizeAreaWB_mm2: 14.7; Value_Code: R220; U/M: EA; Value: 0.22; EIA_Code: E96; SizeX_mm: 3.2; SizeY_mm: 2.5; SizeZ_mm: 1.35; Value2: 0.5W; SizeArea_mm2: 8; VDC_V: 0V; AEC Category: Q200
R12 R28 = CMP-0026436-2: RES, 511, 1%, 0.063 W, AEC-Q200 Grade 0, 0402; Manufacturer: Vishay-Dale; Power_W: 63mW; TempCo: 100 ppm/C; Value_Code: 511R; Value: 511; EIA_Code: E96; SizeX_mm: 1; SizeY_mm: 0.5; SizeZ_mm: 0.6; Value2: 0.063W; AEC Qualified: Y; VDC_V: 50V; AEC Category: Q200; AEC Grade: 0
R13 R15 = CMP-0026213-2: RES, 27.4 k, 1%, 0.063 W, AEC-Q200 Grade 0, 0402; Manufacturer: Vishay-Dale; Power_W: 63mW; TempCo: 100 ppm/C; Value_Code: 27k4; Value: 27.4k; EIA_Code: E96; SizeX_mm: 1; SizeY_mm: 0.5; SizeZ_mm: 0.6; Value2: 0.063W; AEC Qualified: Y; VDC_V: 50V; AEC Category: Q200; AEC Grade: 0
R14 = CMP-0026027-3: RES, 15.0 k, 1%, 0.063 W, AEC-Q200 Grade 0, 0402; Manufacturer: Vishay-Dale; Power_W: 63mW; TempCo: 100 ppm/C; Value_Code: 15k0; Value: 15.0k; EIA_Code: E96; Res_ohm: 15k; SizeX_mm: 1; SizeY_mm: 0.5; SizeZ_mm: 0.6; Value2: 0.063W; AEC Qualified: Y; VDC_V: 50V; AEC Category: Q200; AEC Grade: 0
R16 = CMP-0026071-3: RES, 1.00 k, 1%, 0.063 W, AEC-Q200 Grade 0, 0402; Manufacturer: Vishay-Dale; Power_W: 63mW; TempCo: 100 ppm/C; Value_Code: 1k00; Value: 1.00k; EIA_Code: E96; Res_ohm: 1k; SizeX_mm: 1; SizeY_mm: 0.5; SizeZ_mm: 0.6; Value2: 0.063W; AEC Qualified: Y; VDC_V: 50V; AEC Category: Q200; AEC Grade: 0
R17 = CMP-0026229-2: RES, 25.5 k, 1%, 0.063 W, 0402; Manufacturer: Vishay-Dale; Power_W: 63mW; TempCo: 100 ppm/C; Value_Code: 2k10; Value: 2.10k; EIA_Code: E96; SizeX_mm: 1; SizeY_mm: 0.5; SizeZ_mm: 0.6; Value2: 0.063W; AEC Qualified: Y; VDC_V: 50V; AEC Category: Q200; AEC Grade: 0
R18 = CMP-0027004-2: RES, 0, 5%, 0.063 W, 0402; Manufacturer: Yageo America; Power_W: 63mW; TempCo: 200 ppm/C; Value_Code: 0000; U/M: EA; Value: 0; EIA_Code: E24; SizeX_mm: 1; SizeY_mm: 0.5; SizeZ_mm: 0.6; Value2: 0.063W; VDC_V: 50V; AEC Category: Q200
R19 = CMP-1011-00001-2: RES, 0, 5%, 0.063 W, 0402; Manufacturer: Yageo / Phycomp
R21 = CMP-0026162-2: RES, 20.0 k, 1%, 0.063 W, AEC-Q200 Grade 0, 0402; Manufacturer: Vishay-Dale; Power_W: 63mW; TempCo: 100 ppm/C; Value_Code: 20k0; Value: 20.0k; EIA_Code: E96; Res_ohm: 20k; SizeX_mm: 1; SizeY_mm: 0.5; SizeZ_mm: 0.6; Value2: 0.063W; AEC Qualified: Y; VDC_V: 50V; AEC Category: Q200; AEC Grade: 0
R22 = CMP-1011-00620-2: RES, 9.31 k, 1%, 0.063 W, 0402; Manufacturer: Panasonic
R23 = CMP-0026301-2: RES, 340, 1%, 0.063 W, AEC-Q200 Grade 0, 0402; Manufacturer: Vishay-Dale; Power_W: 63mW; TempCo: 100 ppm/C; Value_Code: 340R; Value: 340; EIA_Code: E96; SizeX_mm: 1; SizeY_mm: 0.5; SizeZ_mm: 0.6; Value2: 0.063W; AEC Qualified: Y; VDC_V: 50V; AEC Category: Q200; AEC Grade: 0
R24 = CMP-0026063-3: RES, 191 k, 1%, 0.063 W, AEC-Q200 Grade 0, 0402; Manufacturer: Vishay-Dale; Power_W: 63mW; TempCo: 100 ppm/C; Value: 191k; EIA_Code: E96; SizeX_mm: 1; SizeY_mm: 0.5; SizeZ_mm: 0.6; Value2: 0.063W; AEC Qualified: Y; VDC_V: 50V; AEC Category: Q200; AEC Grade: 0
R25 = CMP-0026327-2: RES, 39.2 k, 1%, 0.063 W, AEC-Q200 Grade 0, 0402; Manufacturer: Vishay-Dale; Power_W: 63mW; TempCo: 100 ppm/C; Value_Code: 39k2; Value: 39.2k; EIA_Code: E96; SizeX_mm: 1; SizeY_mm: 0.5; SizeZ_mm: 0.6; Value2: 0.063W; AEC Qualified: Y; VDC_V: 50V; AEC Category: Q200; AEC Grade: 0
R26 = CMP-0078669-1: RES, 10.0 k, 1%, 0.063 W, 0402; Manufacturer: Yageo America; Power_W: 63mW; Green_Lifecycle: Active; TempCo: 100 ppm/C; Value_Code: 10k0; Green_REACh: Passed; Value: 10.0k; EIA_Code: E96; Res_ohm: 10k; SizeX_mm: 1; SizeY_mm: 0.5; SizeZ_mm: 0.6; Value2: 0.063W; AEC Qualified: N; AEC Category: Q200
R27 = CMP-0026333-2: RES, 3.32 k, 1%, 0.063 W, AEC-Q200 Grade 0, 0402; Manufacturer: Vishay-Dale; Power_W: 63mW; TempCo: 100 ppm/C; Value_Code: 3k32; Value: 3.32k; EIA_Code: E96; SizeX_mm: 1; SizeY_mm: 0.5; SizeZ_mm: 0.6; Value2: 0.063W; AEC Qualified: Y; VDC_V: 50V; AEC Category: Q200; AEC Grade: 0
R29 = CMP-0026038-3: RES, 169 k, 1%, 0.063 W, AEC-Q200 Grade 0, 0402; Manufacturer: Vishay-Dale; Power_W: 63mW; TempCo: 100 ppm/C; Value: 169k; EIA_Code: E96; SizeX_mm: 1; SizeY_mm: 0.5; SizeZ_mm: 0.6; Value2: 0.063W; AEC Qualified: Y; VDC_V: 50V; AEC Category: Q200; AEC Grade: 0
R30 = CMP-0026023-3: RES, 154 k, 1%, 0.063 W, AEC-Q200 Grade 0, 0402; Manufacturer: Vishay-Dale; Power_W: 63mW; TempCo: 100 ppm/C; Value: 154k; EIA_Code: E96; SizeX_mm: 1; SizeY_mm: 0.5; SizeZ_mm: 0.6; Value2: 0.063W; AEC Qualified: Y; VDC_V: 50V; AEC Category: Q200; AEC Grade: 0
R31 = CMP-0026609-3: RES, 93.1 k, 1%, 0.063 W, AEC-Q200 Grade 0, 0402; Manufacturer: Vishay-Dale; VDC_V: 50V; Value: 93.1k; SizeArea_mm2: 0.5; SizeX_mm: 1; AEC Qualified: Y; Value_Code: 93k1; EIA_Code: E96; AEC Category: Q200; TempCo: 100 ppm/C; Value2: 0.063W; AEC Grade: 0; SizeZ_mm: 0.6; Power_W: 63mW
R32 = CMP-0026859-2: RES, 1.0 M, 5%, 0.063 W, AEC-Q200 Grade 0, 0402; Manufacturer: Vishay-Dale; Power_W: 63mW; TempCo: 200 ppm/C; Value_Code: 1M00; Value: 1.0Meg; EIA_Code: E24; Res_ohm: 1M; SizeX_mm: 1; SizeY_mm: 0.5; SizeZ_mm: 0.6; Value2: 0.063W; AEC Qualified: Y; VDC_V: 50V; AEC Category: Q200; AEC Grade: 0
R33 = CMP-0026591-2: RES, 8.66 k, 1%, 0.063 W, AEC-Q200 Grade 0, 0402; Manufacturer: Vishay-Dale; Power_W: 63mW; TempCo: 100 ppm/C; Value_Code: 8k66; Value: 8.66k; EIA_Code: E96; SizeX_mm: 1; SizeY_mm: 0.5; SizeZ_mm: 0.6; Value2: 0.063W; AEC Qualified: Y; VDC_V: 50V; AEC Category: Q200; AEC Grade: 0
R34 = CMP-0081856-1: RES, 0, 0%, 0.2 W, AEC-Q200 Grade 0, 0402; Manufacturer: Vishay-Dale; SizeAreaWB_mm2: 3; SizeArea_mm2: 0.5; AEC Qualified: Y; AEC Category: Q200; Value: 0; SizeZ_mm: 0.6; Power_W: 200mW; VDC_V: 50V; Value2: 0.2W; SizeX_mm: 1
R36 = CMP-0026367-2: RES, 40.2 k, 1%, 0.063 W, AEC-Q200 Grade 0, 0402; Manufacturer: Vishay-Dale; Power_W: 63mW; TempCo: 100 ppm/C; Value_Code: 40k2; Value: 40.2k; EIA_Code: E96; SizeX_mm: 1; SizeY_mm: 0.5; SizeZ_mm: 0.6; Value2: 0.063W; AEC Qualified: Y; VDC_V: 50V; AEC Category: Q200; AEC Grade: 0
R37 R38 = CMP-0093609-1: 0Ω ±0 0.25W 1206 Thick Film Chip Resistor AEC-Q200 compliant; Manufacturer: Stackpole Electronics; AEC Qualified: Yes; Value: 0; VDC_V: 200V; AEC Grade: Grade 0; Power_W: 250mW; SizeZ_mm: 0.7mm
RT1 = CMP-0002523-3: Thermistor NTC, 47k ohm, 5%, 0603; Manufacturer: MuRata; TaMax_C: 125°C; SizeX_mm: 1.6; SizeY_mm: 0.8; TaMin_C: -40°C; Power_W: 100mW; SizeZ_mm: 1; SizeArea_mm2: 1.28; SizeAreaWB_mm2: 4.68; U/M: EA
T1 = CMP-0097858-1: HIGH EFFICIECNY FLYBACK TRANSFORMER, PMP23331; Manufacturer: Renco Electronics; Ind_H: 300µH; Voltage_Isolation_Vrms: 3kV; DCR_ohm: 0.8; Ns1toNp: 1:0.212/1:0.151/1:0.151; AEC Qualified: No; SizeZ_mm: 1.2inch
TP1 TP3 = CMP-0055149-1: Test Point, Multipurpose, White, TH; Manufacturer: Keystone; CNHeader: FALSE; Green_Lifecycle: Active; Green_REACh: Passed; ContactFinish: Silver; CT: TRUE
TP2 = CMP-0055148-1: Test Point, Multipurpose, Black, TH; Manufacturer: Keystone; CNHeader: FALSE; Green_Lifecycle: Active; Green_REACh: Passed; ContactFinish: Silver; CT: TRUE
U1 = CMP-0092521-4: 3-V to 17-V, 300mA Low IQ Buck Converter in SOT583 Package; Manufacturer: Texas Instruments; Max Supply Voltage: 17V; AEC Grade: NA; CompType: IC; Min Supply Voltage: 3V; Nominal Supply Current: 5mA; Output Voltage: 0.4-5.5V; SizeZ_mm: 0.6mm; Number Of Outputs: 1; AEC Category: Q200; Switching Frequency: 1/2.5MHz; TJmax_C: +150°C; AEC Qualified: No; Standoff Height: 0mm; Output Type: AdjustableProgrammable; Max Duty Cycle: 100%
U2 = CMP-0860377-2: 4-A/6-A, Single-Channel Reinforced Isolation Gate Driver with High Noise Immunity, DWV0008A (SOIC-8); Manufacturer: Texas Instruments; SizeX_mm: 11.5; SizeArea_mm2: 67.275; SizeAreaWB_mm2: 105.975; CompType: IC; SizeZ_mm: 2.8; SizeY_mm: 5.85; AEC Category: Q200; AEC Qualified: N
U3 = CMP-0094229-1: Zero-Voltage-Switching Flyback Controller with Dedicated Synchronous Rectifier Gate-Drive; Manufacturer: Texas Instruments; Nominal Supply Current: 235-3000uA; Standoff Height: 0mm; Output Type: Other; Min Supply Voltage: 14V; TaMax_C: +125°C; TaMin_C: -40°C; Max Supply Voltage: 34V; SizeZ_mm: 0.8mm; Switching Frequency: 1.5kHz; AEC Grade: Grade 1; Number Of Outputs: 1; AEC Qualified: Yes; TJmax_C: +140°C
U4 = CMP-0087394-2: Optoisolator Transistor Output 5000Vrms 1 Channel 6-SO; Manufacturer: Toshiba; CTR (Max): 300%; CTR (Min): 100%; SizeZ_mm: 2.3mm
U5 = CMP-0066199-1: 2.5V Low Iq Adjustable Precision Shunt Regulator, DBZ0003A (SOT-23-3); Manufacturer: Texas Instruments; SizeArea_mm2: 7.5; SizeAreaWB_mm2: 14.0; SizeX_mm: 2.5; SizeY_mm: 3.0; SizeZ_mm: 1.12; CompType: IC; U/M: EA

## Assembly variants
001: not fitted C12 C19 C24 C28 C29 D9 D10 D11 Q4 Q5 R4 R15 R16 R20 R28 R32 R37 R38 R39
